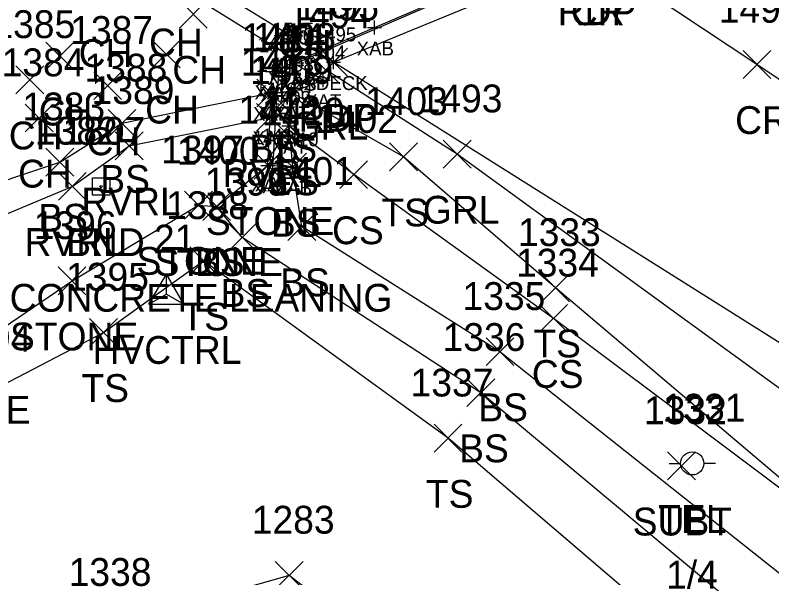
# Model space of a CAD drawing. Extents: x 1537342 to 1542195, y 163002 to 168596.
# Drawn here: x 1541772.7 to 1541827.1, y 163274.1 to 163314.5 of the extents above; entities that cross this region are included whole.
import ezdxf

# ---------------------------------------------------------------- set-up
doc = ezdxf.new("R2010")
doc.units = 0
for name, color, linetype in [('B_A', 7, 'Continuous'), ('B_I', 7, 'Continuous'), ('B_TIC', 7, 'Continuous'), ('BELB', 7, 'Continuous'), ('BF', 7, 'Continuous'), ('BSE', 7, 'Continuous'), ('BSUBM', 7, 'Continuous'), ('C_A', 7, 'Continuous'), ('C_I', 7, 'Continuous'), ('CPSM', 7, 'Continuous'), ('L_A', 7, 'Continuous'), ('L_I', 7, 'Continuous'), ('L_TIC', 7, 'Continuous'), ('LASF', 7, 'Continuous'), ('LAWA', 7, 'Continuous'), ('LAWE', 7, 'Continuous'), ('LELB', 7, 'Continuous'), ('M_A', 7, 'Continuous'), ('M_C', 7, 'Continuous'), ('M_I', 7, 'Continuous'), ('MHBP', 7, 'Continuous'), ('P_A', 7, 'Continuous'), ('P_I', 7, 'Continuous'), ('P_TIC', 7, 'Continuous'), ('PET', 7, 'Continuous'), ('PRC', 7, 'Continuous'), ('R_A', 7, 'Continuous'), ('R_I', 7, 'Continuous'), ('R_TIC', 7, 'Continuous'), ('RGR', 7, 'Continuous'), ('U_A', 7, 'Continuous'), ('U_C', 7, 'Continuous'), ('U_I', 7, 'Continuous'), ('U_TIC', 7, 'Continuous'), ('UP', 7, 'Continuous')]:
    doc.layers.add(name, color=color, linetype=linetype)

msp = doc.modelspace()

# ---------------------------------------------------------------- linework, layer by layer
at = {"layer": 'B_TIC'}
for p, q in [((1541798.524, 163313.65), (1541798.6, 163313.65)), ((1541792.557, 163311.514), (1541792.632, 163311.514)), ((1541792.956, 163311.111), (1541793.031, 163311.111)), ((1541795.582, 163311.161), (1541795.658, 163311.161)), ((1541792.948, 163310.941), (1541793.023, 163310.941)), ((1541791.188, 163310.492), (1541791.264, 163310.492)), ((1541791.642, 163310.38), (1541791.718, 163310.38)), ((1541794.834, 163309.864), (1541794.91, 163309.864)), ((1541794.834, 163309.864), (1541794.91, 163309.864)), ((1541791.079, 163308.949), (1541791.155, 163308.949)), ((1541791.513, 163308.989), (1541791.589, 163308.989)), ((1541792.57, 163308.982), (1541792.646, 163308.982)), ((1541791.037, 163307.198), (1541791.112, 163307.198)), ((1541792.377, 163306.599), (1541792.453, 163306.599)), ((1541790.868, 163303.749), (1541790.943, 163303.749)), ((1541791.218, 163303.885), (1541791.294, 163303.885)), ((1541791.218, 163303.885), (1541791.294, 163303.885)), ((1541792.636, 163303.617), (1541792.711, 163303.617)), ((1541792.636, 163303.617), (1541792.711, 163303.617))]:
    msp.add_line(p, q, dxfattribs=at)
for points in [[(1541798.521, 163313.15), (1541798.521, 163314.15)], [(1541798.021, 163313.65), (1541799.021, 163313.65)], [(1541792.553, 163311.014), (1541792.553, 163312.014)], [(1541795.579, 163310.661), (1541795.579, 163311.661)], [(1541792.053, 163311.514), (1541793.053, 163311.514)], [(1541792.452, 163311.111), (1541793.452, 163311.111)], [(1541792.944, 163310.441), (1541792.944, 163311.441)], [(1541792.952, 163310.611), (1541792.952, 163311.611)], [(1541795.079, 163311.161), (1541796.079, 163311.161)], [(1541791.185, 163309.992), (1541791.185, 163310.992)], [(1541791.639, 163309.88), (1541791.639, 163310.88)], [(1541792.444, 163310.941), (1541793.444, 163310.941)], [(1541790.685, 163310.492), (1541791.685, 163310.492)], [(1541791.139, 163310.38), (1541792.139, 163310.38)], [(1541794.831, 163309.364), (1541794.831, 163310.364)], [(1541794.831, 163309.364), (1541794.831, 163310.364)], [(1541791.51, 163308.489), (1541791.51, 163309.489)], [(1541792.567, 163308.482), (1541792.567, 163309.482)], [(1541794.331, 163309.864), (1541795.331, 163309.864)], [(1541794.331, 163309.864), (1541795.331, 163309.864)], [(1541790.576, 163308.949), (1541791.576, 163308.949)], [(1541791.01, 163308.989), (1541792.01, 163308.989)], [(1541791.076, 163308.449), (1541791.076, 163309.449)], [(1541792.067, 163308.982), (1541793.067, 163308.982)], [(1541791.033, 163306.698), (1541791.033, 163307.698)], [(1541790.533, 163307.198), (1541791.533, 163307.198)], [(1541792.374, 163306.099), (1541792.374, 163307.099)], [(1541791.874, 163306.599), (1541792.874, 163306.599)], [(1541790.864, 163303.249), (1541790.864, 163304.249)], [(1541791.215, 163303.385), (1541791.215, 163304.385)], [(1541791.215, 163303.385), (1541791.215, 163304.385)], [(1541792.632, 163303.117), (1541792.632, 163304.117)], [(1541792.632, 163303.117), (1541792.632, 163304.117)], [(1541790.364, 163303.749), (1541791.364, 163303.749)], [(1541790.715, 163303.885), (1541791.715, 163303.885)], [(1541790.715, 163303.885), (1541791.715, 163303.885)], [(1541792.132, 163303.617), (1541793.132, 163303.617)], [(1541792.132, 163303.617), (1541793.132, 163303.617)]]:
    msp.add_lwpolyline(points, dxfattribs=at)
at = {"layer": 'BELB'}
msp.add_lwpolyline([(1541795.579, 163311.161), (1541767.135, 163328.632)], dxfattribs=at)
at = {"layer": 'BF'}
msp.add_lwpolyline([(1541767.818, 163326.884), (1541792.553, 163311.514)], dxfattribs=at)
at = {"layer": 'BSE'}
msp.add_lwpolyline([(1541792.952, 163311.111), (1541808.652, 163317.928), (1541808.857, 163318.004), (1541831.221, 163327.864)], dxfattribs=at)
at = {"layer": 'BSUBM'}
for points in [[(1541792.632, 163303.617), (1541790.864, 163303.749), (1541791.033, 163307.198), (1541791.076, 163308.949), (1541791.185, 163310.492), (1541798.521, 163313.65), (1541805.481, 163316.659), (1541805.688, 163316.76), (1541820.303, 163323.059), (1541830.941, 163327.84), (1541831.268, 163327.91)], [(1541794.831, 163309.864), (1541792.944, 163310.941), (1541791.639, 163310.38), (1541791.51, 163308.989), (1541791.215, 163303.885)], [(1541794.831, 163309.864), (1541792.567, 163308.982), (1541792.374, 163306.599), (1541792.632, 163303.617), (1541791.215, 163303.885)]]:
    msp.add_lwpolyline(points, dxfattribs=at)
at = {"layer": 'CPSM'}
for p, q in [((1541782.319, 163293.76), (1541783.569, 163295.925)), ((1541784.819, 163293.76), (1541783.569, 163295.925)), ((1541783.569, 163294.481), (1541783.569, 163295.925)), ((1541782.319, 163293.76), (1541783.569, 163294.481)), ((1541783.569, 163294.481), (1541783.569, 163294.481)), ((1541783.569, 163294.481), (1541784.819, 163293.76)), ((1541782.319, 163293.76), (1541784.819, 163293.76))]:
    msp.add_line(p, q, dxfattribs=at)
at = {"layer": 'L_TIC'}
for points in [[(1541784.502, 163313.612), (1541786.502, 163315.612)], [(1541786.502, 163313.612), (1541784.502, 163315.612)], [(1541782.556, 163310.756), (1541784.556, 163312.756)], [(1541784.556, 163310.756), (1541782.556, 163312.756)], [(1541774.91, 163310.614), (1541776.91, 163312.614)], [(1541776.91, 163310.614), (1541774.91, 163312.614)], [(1541772.763, 163308.895), (1541774.763, 163310.895)], [(1541774.763, 163308.895), (1541772.763, 163310.895)], [(1541778.353, 163308.477), (1541780.353, 163310.477)], [(1541780.353, 163308.477), (1541778.353, 163310.477)], [(1541790.076, 163307.949), (1541792.076, 163309.949)], [(1541792.076, 163307.949), (1541790.076, 163309.949)], [(1541791.567, 163307.982), (1541793.567, 163309.982)], [(1541793.567, 163307.982), (1541791.567, 163309.982)], [(1541773.427, 163306.153), (1541775.427, 163308.153)], [(1541775.427, 163306.153), (1541773.427, 163308.153)], [(1541790.033, 163306.198), (1541792.033, 163308.198)], [(1541792.033, 163306.198), (1541790.033, 163308.198)], [(1541779.379, 163305.769), (1541781.379, 163307.769)], [(1541781.379, 163305.769), (1541779.379, 163307.769)], [(1541791.374, 163305.599), (1541793.374, 163307.599)], [(1541793.374, 163305.599), (1541791.374, 163307.599)], [(1541779.896, 163304.154), (1541781.896, 163306.154)], [(1541781.896, 163304.154), (1541779.896, 163306.154)], [(1541799.604, 163303.36), (1541801.604, 163305.36)], [(1541801.604, 163303.36), (1541799.604, 163305.36)], [(1541774.915, 163302.982), (1541776.915, 163304.982)], [(1541776.915, 163302.982), (1541774.915, 163304.982)], [(1541789.864, 163302.749), (1541791.864, 163304.749)], [(1541791.864, 163302.749), (1541789.864, 163304.749)], [(1541791.632, 163302.617), (1541793.632, 163304.617)], [(1541793.632, 163302.617), (1541791.632, 163304.617)], [(1541796.026, 163302.082), (1541798.026, 163304.082)], [(1541798.026, 163302.082), (1541796.026, 163304.082)], [(1541775.81, 163301.235), (1541777.81, 163303.235)], [(1541777.81, 163301.235), (1541775.81, 163303.235)], [(1541784.876, 163299.883), (1541786.876, 163301.883)], [(1541786.876, 163299.883), (1541784.876, 163301.883)], [(1541786.179, 163299.797), (1541788.179, 163301.797)], [(1541788.179, 163299.797), (1541786.179, 163301.797)], [(1541786.179, 163299.797), (1541788.179, 163301.797)], [(1541788.179, 163299.797), (1541786.179, 163301.797)], [(1541792.299, 163298.343), (1541794.299, 163300.343)], [(1541794.299, 163298.343), (1541792.299, 163300.343)], [(1541788.025, 163297.575), (1541790.025, 163299.575)], [(1541790.025, 163297.575), (1541788.025, 163299.575)], [(1541785.245, 163295.885), (1541787.245, 163297.885)], [(1541787.245, 163295.885), (1541785.245, 163297.885)], [(1541785.245, 163295.885), (1541787.245, 163297.885)], [(1541787.245, 163295.885), (1541785.245, 163297.885)], [(1541775.791, 163294.449), (1541777.791, 163296.449)], [(1541777.791, 163294.449), (1541775.791, 163296.449)], [(1541810.52, 163293.945), (1541812.52, 163295.945)], [(1541812.52, 163293.945), (1541810.52, 163295.945)], [(1541810.381, 163291.753), (1541812.381, 163293.753)], [(1541812.381, 163291.753), (1541810.381, 163293.753)], [(1541778.056, 163290.741), (1541780.056, 163292.741)], [(1541780.056, 163290.741), (1541778.056, 163292.741)], [(1541806.534, 163289.354), (1541808.534, 163291.354)], [(1541808.534, 163289.354), (1541806.534, 163291.354)], [(1541805.16, 163286.408), (1541807.16, 163288.408)], [(1541807.16, 163286.408), (1541805.16, 163288.408)], [(1541802.805, 163283.137), (1541804.805, 163285.137)], [(1541804.805, 163283.137), (1541802.805, 163285.137)], [(1541791.396, 163273.279), (1541793.396, 163275.279)], [(1541793.396, 163273.279), (1541791.396, 163275.279)]]:
    msp.add_lwpolyline(points, dxfattribs=at)
at = {"layer": 'LASF'}
msp.add_lwpolyline([(1541752.386, 163275.426), (1541761.478, 163286.268), (1541769.05, 163290.174), (1541776.791, 163295.449), (1541785.876, 163300.883), (1541787.179, 163300.797), (1541790.864, 163303.749)], dxfattribs=at)
at = {"layer": 'LAWA'}
msp.add_lwpolyline([(1541844.856, 163168.927), (1541849.554, 163183.808), (1541839.113, 163205.97), (1541817.649, 163223.226), (1541815.003, 163239.805), (1541816.556, 163255.639), (1541792.396, 163274.279), (1541779.243, 163270.522), (1541762.882, 163259.76), (1541752.386, 163275.426), (1541738.683, 163268.208), (1541722.173, 163262.13), (1541701.078, 163257.123)], dxfattribs=at)
at = {"layer": 'LAWE'}
msp.add_lwpolyline([(1541697.567, 163262.542), (1541711.727, 163266.963), (1541730.099, 163271.239), (1541739.509, 163276.959), (1541746.473, 163282.876), (1541755.026, 163290.887), (1541767.29, 163298.255), (1541776.81, 163302.235), (1541780.896, 163305.154), (1541791.033, 163307.198)], dxfattribs=at)
at = {"layer": 'LELB'}
for points in [[(1541697.383, 163265.202), (1541711.185, 163268.467), (1541728.727, 163272.935), (1541738.542, 163278.299), (1541744.939, 163284.528), (1541750.449, 163291.776), (1541762.364, 163297.061), (1541764.631, 163298.709), (1541768.936, 163301.664), (1541775.915, 163303.982), (1541780.379, 163306.769), (1541791.076, 163308.949)], [(1541981.521, 163166.612), (1541978.593, 163174.423), (1541956.984, 163190.155), (1541924.161, 163215.176), (1541866.464, 163254.002), (1541852.645, 163260.979), (1541835.078, 163274.973), (1541811.52, 163294.945), (1541800.604, 163304.36), (1541792.567, 163308.982)], [(1541955.886, 163187.244), (1541923.009, 163213.535), (1541863.649, 163251.537), (1541850.665, 163258.713), (1541835.078, 163274.973), (1541811.381, 163292.753), (1541797.026, 163303.082), (1541792.374, 163306.599)], [(1541982.352, 163154.541), (1541977.461, 163162.706), (1541976.488, 163171.882), (1541973.522, 163173.984), (1541972.191, 163175.206), (1541955.886, 163187.244), (1541919.334, 163210.017), (1541893.735, 163229.08), (1541863.644, 163247.964), (1541848.889, 163252.659), (1541830.956, 163271.76), (1541807.534, 163290.354), (1541793.299, 163299.343), (1541792.632, 163303.617)], [(1541920.518, 163124.036), (1541935.157, 163148.54), (1541933.922, 163173.016), (1541915.598, 163197.936), (1541891.22, 163224.516), (1541851.874, 163246.309), (1541828.993, 163268.295), (1541806.16, 163287.408), (1541789.025, 163298.575), (1541787.179, 163300.797)], [(1541761.478, 163286.268), (1541770.616, 163287.35), (1541779.056, 163291.741), (1541786.245, 163296.885)], [(1541912.531, 163131.424), (1541928.998, 163149.961), (1541922.933, 163163.15), (1541906.573, 163185.358), (1541883.884, 163218.475), (1541847.29, 163243.176), (1541824.829, 163266.159), (1541803.805, 163284.137), (1541786.245, 163296.885)]]:
    msp.add_lwpolyline(points, dxfattribs=at)
at = {"layer": 'MHBP'}
msp.add_lwpolyline([(1541778.253, 163302.853), (1541779.503, 163302.853), (1541779.503, 163301.603), (1541778.253, 163301.603)], close=True, dxfattribs=at)
msp.add_circle((1541778.878, 163302.228), 0.0833, dxfattribs=at)
at = {"layer": 'P_TIC'}
for points in [[(1541794.579, 163310.161), (1541796.579, 163312.161)], [(1541796.579, 163310.161), (1541794.579, 163312.161)], [(1541824.993, 163310.002), (1541826.993, 163312.002)], [(1541826.993, 163310.002), (1541824.993, 163312.002)]]:
    msp.add_lwpolyline(points, dxfattribs=at)
at = {"layer": 'PET'}
msp.add_lwpolyline([(1542165.564, 163030.05), (1542126.673, 163058.359), (1542096.316, 163082.469), (1542058.609, 163112.541), (1542052.024, 163117.841), (1542010.734, 163151.352), (1541978.729, 163177.477), (1541958.58, 163193.326), (1541928.576, 163217.895), (1541894.651, 163244.61), (1541857.529, 163271.038), (1541839.599, 163283.446), (1541795.579, 163311.161), (1541814.195, 163318.824), (1541832.215, 163326.687)], dxfattribs=at)
at = {"layer": 'PRC'}
msp.add_lwpolyline([(1542174.182, 163041.839), (1542135.376, 163070.507), (1542102.151, 163097.417), (1542058.019, 163132.978), (1542032.763, 163153.879), (1541982.814, 163194.284), (1541947.346, 163222.574), (1541904.323, 163256.107), (1541874.287, 163278.529), (1541825.993, 163311.002), (1541814.195, 163318.824)], dxfattribs=at)
at = {"layer": 'R_TIC'}
for points in [[(1541794.025, 163309.604), (1541796.025, 163311.604)], [(1541796.025, 163309.604), (1541794.025, 163311.604)], [(1541803.453, 163303.558), (1541805.453, 163305.558)], [(1541805.453, 163303.558), (1541803.453, 163305.558)]]:
    msp.add_lwpolyline(points, dxfattribs=at)
at = {"layer": 'RGR'}
msp.add_lwpolyline([(1541857.755, 163264.153), (1541837.865, 163280.265), (1541804.453, 163304.558), (1541795.025, 163310.604)], dxfattribs=at)
at = {"layer": 'U_TIC'}
for points in [[(1541819.571, 163281.147), (1541821.571, 163283.147)], [(1541821.571, 163281.147), (1541819.571, 163283.147)]]:
    msp.add_lwpolyline(points, dxfattribs=at)
at = {"layer": 'UP'}
for p, q in [((1541819.686, 163282.324), (1541820.511, 163282.324)), ((1541821.345, 163282.329), (1541821.345, 163282.329)), ((1541823.011, 163282.329), (1541822.178, 163282.329)), ((1541822.178, 163282.329), (1541822.178, 163282.329)), ((1541823.011, 163282.329), (1541823.011, 163282.329))]:
    msp.add_line(p, q, dxfattribs=at)
msp.add_circle((1541821.345, 163282.329), 0.833, dxfattribs=at)

# ---------------------------------------------------------------- texts
at = {"layer": 'B_A'}
for s, p in [('XAB', (1541797.241, 163311.65)), ('XFAB', (1541790.825, 163309.514)), ('XBS', (1541791.692, 163309.111)), ('XDECK', (1541793.421, 163309.161)), ('XAB', (1541789.905, 163308.492)), ('XAT', (1541791.649, 163308.941)), ('XAT', (1541790.344, 163308.38)), ('XAT', (1541793.536, 163307.864)), ('XAT', (1541793.536, 163307.864)), ('XAB', (1541789.796, 163306.949)), ('XAT', (1541790.215, 163306.989)), ('XAT', (1541791.272, 163306.982)), ('XAB', (1541789.754, 163305.198)), ('XAT', (1541791.078, 163304.599)), ('XAB', (1541789.585, 163301.749)), ('XAT', (1541789.92, 163301.885)), ('XAT', (1541789.92, 163301.885)), ('XAT', (1541791.337, 163301.617)), ('XAB', (1541791.353, 163301.617))]:
    msp.add_text(s, height=1, dxfattribs=at).set_placement(p)
at = {"layer": 'B_I'}
for s, p in [('1545', (1541791.207, 163313.014)), ('1405', (1541791.559, 163312.441)), ('1561', (1541791.866, 163312.611)), ('1495', (1541794.232, 163312.661)), ('1415', (1541790.122, 163311.992)), ('1406', (1541790.226, 163311.88)), ('1404', (1541793.445, 163311.364)), ('1404', (1541793.445, 163311.364)), ('1414', (1541790.013, 163310.449)), ('1407', (1541790.124, 163310.489)), ('1408', (1541791.181, 163310.482)), ('1413', (1541789.971, 163308.698)), ('1409', (1541790.984, 163308.099)), ('1412', (1541789.801, 163305.249)), ('1411', (1541790.435, 163305.385)), ('1411', (1541790.435, 163305.385)), ('1410', (1541791.526, 163305.117)), ('1410', (1541791.526, 163305.117))]:
    msp.add_text(s, height=1, dxfattribs=at).set_placement(p)
at = {"layer": 'C_A'}
msp.add_text('HVCTRL', height=2, dxfattribs=at).set_placement((1541778.262, 163289.481))
at = {"layer": 'C_I'}
msp.add_text('21', height=2, dxfattribs=at).set_placement((1541782.672, 163297.481))
at = {"layer": 'L_A'}
for s, p in [('CH', (1541782.322, 163311.579)), ('CH', (1541791.572, 163311.483)), ('CH', (1541777.266, 163310.819)), ('CH', (1541783.991, 163309.612)), ('CH', (1541774.398, 163306.614)), ('CH', (1541782.044, 163306.756)), ('CH', (1541772.251, 163304.895)), ('CH', (1541777.841, 163304.477)), ('BS', (1541789.517, 163303.949)), ('TS', (1541790.976, 163303.982)), ('CH', (1541772.915, 163302.153)), ('RVRL', (1541787.6, 163302.198)), ('BS', (1541778.82, 163301.769)), ('CS', (1541790.815, 163301.599)), ('RVRL', (1541777.463, 163300.154)), ('TS', (1541799.014, 163299.36)), ('BS', (1541774.355, 163298.982)), ('STONE', (1541786.408, 163298.749)), ('BS', (1541791.073, 163298.617)), ('CS', (1541795.467, 163298.082)), ('RVRL', (1541773.377, 163297.235)), ('STONE', (1541781.419, 163295.883)), ('STONE', (1541782.722, 163295.797)), ('BS', (1541785.62, 163295.797)), ('BS', (1541791.74, 163294.343)), ('BS', (1541787.466, 163293.575)), ('TS', (1541784.655, 163291.885)), ('TS', (1541784.655, 163291.885)), ('STONE', (1541772.334, 163290.449)), ('TS', (1541809.93, 163289.945)), ('CS', (1541809.822, 163287.753)), ('TS', (1541777.466, 163286.741)), ('STONE', (1541764.594, 163285.174)), ('BS', (1541805.975, 163285.354)), ('BS', (1541804.601, 163282.408)), ('TS', (1541802.214, 163279.137))]:
    msp.add_text(s, height=2, dxfattribs=at).set_placement(p)
at = {"layer": 'L_I'}
for s, p in [('1385', (1541771.07, 163312.895)), ('1387', (1541776.66, 163312.477)), ('1414', (1541788.95, 163311.949)), ('1408', (1541789.795, 163311.982)), ('1413', (1541788.908, 163310.198)), ('1384', (1541771.734, 163310.153)), ('1388', (1541777.686, 163309.769)), ('1409', (1541789.594, 163309.599)), ('1389', (1541778.195, 163308.154)), ('1383', (1541773.222, 163306.982)), ('1403', (1541797.833, 163307.36)), ('1412', (1541788.739, 163306.749)), ('1410', (1541790.42, 163306.617)), ('1402', (1541794.255, 163306.082)), ('1382', (1541774.117, 163305.235)), ('1397', (1541783.183, 163303.883)), ('1400', (1541784.32, 163303.797)), ('1400', (1541784.32, 163303.797)), ('1401', (1541791.095, 163302.343)), ('1399', (1541786.324, 163301.575)), ('1398', (1541783.552, 163299.885)), ('1398', (1541783.552, 163299.885)), ('1396', (1541774.043, 163298.449)), ('1333', (1541808.828, 163297.945)), ('1334', (1541808.688, 163295.753)), ('1395', (1541776.363, 163294.741)), ('1335', (1541804.841, 163293.354)), ('1394', (1541767.923, 163290.35)), ('1336', (1541803.412, 163290.408)), ('1337', (1541801.112, 163287.137)), ('1283', (1541789.703, 163277.279)), ('1338', (1541776.55, 163273.522))]:
    msp.add_text(s, height=2, dxfattribs=at).set_placement(p)
at = {"layer": 'M_A'}
msp.add_text('BND', height=2, dxfattribs=at).set_placement((1541776.366, 163297.228))
at = {"layer": 'M_C'}
msp.add_text('4"X4" 3.5\' AGS CONCRETE LEANING', height=2, dxfattribs=at).set_placement((1541753.548, 163293.228))
at = {"layer": 'M_I'}
msp.add_text('1807', height=2, dxfattribs=at).set_placement((1541776.106, 163305.228))
at = {"layer": 'P_A'}
for s, p in [('RDP', (1541811.683, 163313.824)), ('CR', (1541812.628, 163313.824)), ('RDP', (1541793.067, 163306.161)), ('CR', (1541824.426, 163306.002))]:
    msp.add_text(s, height=2, dxfattribs=at).set_placement(p)
at = {"layer": 'P_I'}
for s, p in [('1495', (1541792.886, 163314.161)), ('1496', (1541823.245, 163314.002))]:
    msp.add_text(s, height=2, dxfattribs=at).set_placement(p)
at = {"layer": 'R_A'}
for p in [(1541792.568, 163305.604), (1541801.997, 163299.558)]:
    msp.add_text('GRL', height=2, dxfattribs=at).set_placement(p)
at = {"layer": 'R_I'}
for s, p in [('1494', (1541792.332, 163313.604)), ('1493', (1541801.761, 163307.558))]:
    msp.add_text(s, height=2, dxfattribs=at).set_placement(p)
at = {"layer": 'U_A'}
for s, p in [('SUBT', (1541817.067, 163277.147)), ('TEL', (1541818.904, 163277.329))]:
    msp.add_text(s, height=2, dxfattribs=at).set_placement(p)
at = {"layer": 'U_C'}
msp.add_text('1/4', height=2, dxfattribs=at).set_placement((1541819.471, 163273.329))
at = {"layer": 'U_I'}
for s, p in [('1331', (1541819.219, 163285.329)), ('1332', (1541817.878, 163285.147))]:
    msp.add_text(s, height=2, dxfattribs=at).set_placement(p)

doc.saveas('drawing.dxf')
